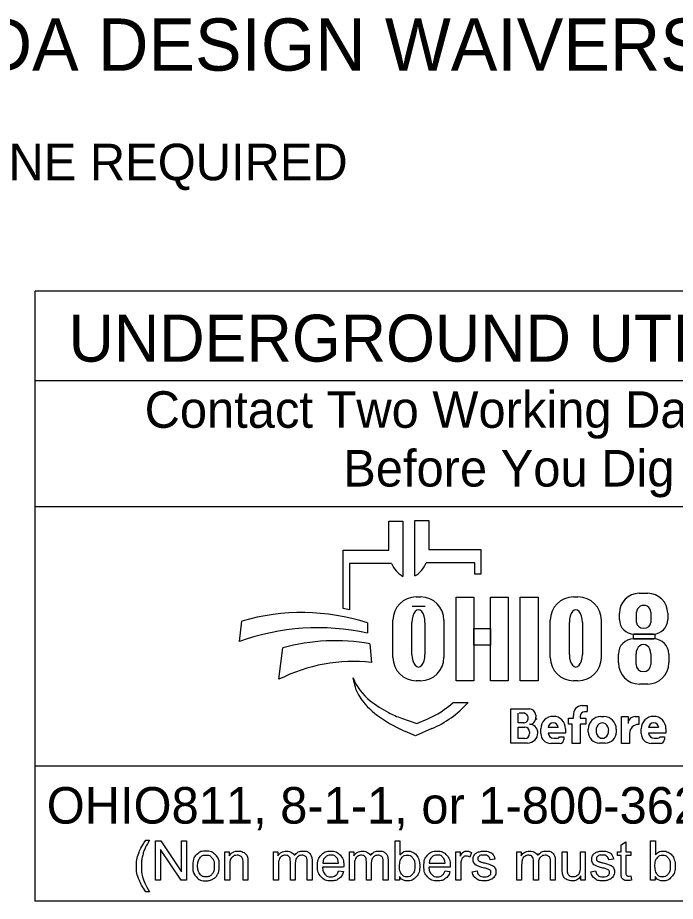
# Model space of a CAD drawing. Extents: x -1.8 to 75.7, y -2 to 25.
# Drawn here: x 44.011 to 46.531, y 3.755 to 7.141 of the extents above; entities that cross this region are included whole.
import ezdxf

# ---------------------------------------------------------------- set-up
doc = ezdxf.new("R2010")
doc.units = 0
doc.layers.add('SH_Data', color=7, linetype='Continuous')
doc.layers.add('SH_Text', color=7, linetype='Continuous')

msp = doc.modelspace()

# ---------------------------------------------------------------- linework, layer by layer
at = {"layer": 'SH_Data'}
for p, q in [((44.0777, 3.7549), (44.0777, 6.0924)), ((48.3277, 6.0924), (44.0777, 6.0924)), ((44.0777, 5.7508), (48.3277, 5.7508)), ((44.0777, 5.2674), (48.3277, 5.2674)), ((48.3277, 4.2727), (44.0777, 4.2727)), ((48.3277, 3.7549), (44.0777, 3.7549))]:
    msp.add_line(p, q, dxfattribs=at)
at = {"layer": 'SH_Text'}
for p, q in [((45.533, 5.0021), (45.533, 5.2142)), ((45.533, 5.2142), (45.5866, 5.2142)), ((45.5866, 5.2142), (45.5866, 5.1027)), ((45.4337, 5.1004), (45.4337, 5.2119)), ((45.4337, 5.2119), (45.4873, 5.2119)), ((45.4873, 5.2119), (45.4873, 4.9998)), ((45.2577, 4.8765), (45.2577, 5.1004)), ((45.2577, 5.1004), (45.4337, 5.1004)), ((45.5866, 5.1027), (45.7859, 5.1027)), ((45.7859, 5.1027), (45.7859, 5.0089)), ((45.283, 5.0489), (45.283, 4.8721)), ((45.4441, 5.0489), (45.283, 5.0489)), ((45.7626, 5.0513), (45.5762, 5.0513)), ((45.7626, 5.0089), (45.7626, 5.0513)), ((45.7859, 5.0089), (45.7626, 5.0089)), ((45.5387, 4.9212), (45.5552, 4.9212)), ((46.1417, 4.9212), (46.1583, 4.9212)), ((46.3933, 4.9352), (46.426, 4.9352)), ((45.572, 4.8842), (45.5222, 4.8842)), ((46.317, 4.8346), (46.317, 4.8589)), ((46.3831, 4.8232), (46.3831, 4.8625)), ((46.4373, 4.8625), (46.4373, 4.8232)), ((46.5023, 4.8589), (46.5023, 4.8346)), ((44.8604, 4.7502), (44.8698, 4.8283)), ((45.351, 4.8218), (45.351, 4.783)), ((45.4492, 4.6897), (45.4492, 4.8317)), ((45.5221, 4.7011), (45.5221, 4.8234)), ((45.5719, 4.8234), (45.5719, 4.7011)), ((45.6447, 4.8317), (45.6447, 4.6897)), ((46.0523, 4.6897), (46.0523, 4.8317)), ((46.1252, 4.7011), (46.1252, 4.8234)), ((46.175, 4.8234), (46.175, 4.7011)), ((46.2477, 4.8317), (46.2477, 4.6897)), ((46.4463, 4.7786), (46.373, 4.7786)), ((45.361, 4.7412), (45.3672, 4.6703)), ((46.3711, 4.7603), (46.4485, 4.7603)), ((45.0122, 4.6057), (45.0269, 4.7258)), ((46.3133, 4.6684), (46.3133, 4.7024)), ((46.3807, 4.6624), (46.3807, 4.7033)), ((46.4376, 4.7033), (46.4376, 4.6624)), ((46.5064, 4.7024), (46.5064, 4.6684)), ((45.2999, 4.5928), (45.2968, 4.6107)), ((45.5552, 4.6002), (45.5387, 4.6002)), ((46.1583, 4.6002), (46.1417, 4.6002)), ((46.4254, 4.5874), (46.3942, 4.5874)), ((45.6802, 4.5169), (45.7376, 4.5169)), ((46.1741, 4.5046), (46.1935, 4.5046)), ((46.1935, 4.5046), (46.1935, 4.4817)), ((45.9015, 4.3611), (45.9015, 4.4919)), ((45.9015, 4.4919), (45.9727, 4.4919)), ((45.9295, 4.4384), (45.9295, 4.4753)), ((45.9547, 4.4753), (45.9334, 4.4753)), ((46.1935, 4.4812), (46.1834, 4.4812)), ((45.4818, 4.4565), (45.5412, 4.436)), ((45.5412, 4.436), (45.5822, 4.4538)), ((45.9489, 4.4384), (45.9295, 4.4384)), ((45.9964, 4.4681), (45.9964, 4.4602)), ((46.1215, 4.4333), (46.1215, 4.4563)), ((46.1215, 4.4563), (46.1408, 4.4563)), ((46.1408, 4.4563), (46.1408, 4.4667)), ((46.1669, 4.4647), (46.1669, 4.4563)), ((46.1669, 4.4563), (46.1884, 4.4563)), ((46.1884, 4.4563), (46.1884, 4.4333)), ((46.2453, 4.4628), (46.2574, 4.4628)), ((46.3255, 4.3599), (46.3255, 4.4626)), ((46.3255, 4.4626), (46.3501, 4.4626)), ((46.3501, 4.4626), (46.3501, 4.4357)), ((46.3773, 4.4626), (46.3912, 4.4626)), ((46.3912, 4.4626), (46.3912, 4.433)), ((45.5352, 4.389), (45.4978, 4.4054)), ((45.5984, 4.4165), (45.5352, 4.389)), ((45.9295, 4.379), (45.9295, 4.4218)), ((45.9295, 4.4218), (45.955, 4.4218)), ((45.9731, 4.4037), (45.9731, 4.3973)), ((46.016, 4.3979), (46.016, 4.4163)), ((46.0826, 4.4203), (46.0441, 4.4203)), ((46.1106, 4.4163), (46.1106, 4.3987)), ((46.1364, 4.4333), (46.1215, 4.4333)), ((46.1364, 4.3599), (46.1364, 4.4333)), ((46.1884, 4.4333), (46.1669, 4.4333)), ((46.1669, 4.4333), (46.1669, 4.3599)), ((46.1975, 4.4042), (46.1975, 4.415)), ((46.3052, 4.415), (46.3052, 4.4042)), ((46.401, 4.3979), (46.401, 4.4163)), ((46.4675, 4.4203), (46.429, 4.4203)), ((46.4955, 4.4163), (46.4955, 4.3987)), ((45.9547, 4.379), (45.9295, 4.379)), ((46.0045, 4.4008), (46.0045, 4.4005)), ((46.1106, 4.3987), (46.0441, 4.3987)), ((46.0651, 4.3794), (46.0792, 4.3794)), ((46.0878, 4.385), (46.1046, 4.385)), ((46.1046, 4.385), (46.1046, 4.3752)), ((46.3561, 4.3981), (46.3561, 4.3599)), ((46.4955, 4.3987), (46.4291, 4.3987)), ((46.45, 4.3794), (46.4641, 4.3794)), ((46.4727, 4.385), (46.4895, 4.385)), ((46.4895, 4.385), (46.4895, 4.3752)), ((45.9651, 4.3611), (45.9015, 4.3611)), ((46.0894, 4.3599), (46.054, 4.3599)), ((46.1669, 4.3599), (46.1364, 4.3599)), ((46.2625, 4.3615), (46.2402, 4.3615)), ((46.3561, 4.3599), (46.3255, 4.3599)), ((46.4743, 4.3599), (46.4389, 4.3599))]:
    msp.add_line(p, q, dxfattribs=at)
for points in [[(45.6911, 4.9201), (45.7591, 4.9201), (45.7591, 4.6002), (45.6911, 4.6002)], [(45.8233, 4.9201), (45.8912, 4.9201), (45.8912, 4.6002), (45.8233, 4.6002)], [(45.9366, 4.9201), (46.0054, 4.9201), (46.0054, 4.6002), (45.9366, 4.6002)], [(45.7591, 4.8003), (45.8233, 4.8003), (45.8233, 4.7363), (45.7591, 4.7363)], [(46.3708, 4.7786), (46.4525, 4.7786), (46.4525, 4.7601), (46.3708, 4.7601)]]:
    msp.add_lwpolyline(points, close=True, dxfattribs=at)
for points in [[(44.5023, 3.9887), (44.5155, 3.9887)], [(44.539, 3.836), (44.539, 3.9862), (44.5594, 3.9862), (44.6384, 3.8682), (44.6384, 3.9862), (44.6574, 3.9862), (44.6574, 3.836), (44.637, 3.836), (44.558, 3.9539), (44.558, 3.836), (44.539, 3.836)], [(45.4745, 3.836), (45.4574, 3.836), (45.4574, 3.9862), (45.4759, 3.9862), (45.4759, 3.9326)], [(46.3234, 3.8679), (46.3234, 3.9305), (46.3098, 3.9305), (46.3098, 3.9448), (46.3234, 3.9448), (46.3234, 3.9718), (46.3419, 3.9828), (46.3419, 3.9448), (46.3603, 3.9448), (46.3603, 3.9305), (46.3419, 3.9305), (46.3419, 3.8668)], [(46.4536, 3.836), (46.4365, 3.836), (46.4365, 3.9862), (46.4549, 3.9862), (46.4549, 3.9326)], [(44.805, 3.836), (44.805, 3.9448), (44.8216, 3.9448), (44.8216, 3.9294)], [(44.9914, 3.836), (44.9914, 3.9448), (45.0079, 3.9448), (45.0079, 3.9295)], [(45.2828, 3.836), (45.2828, 3.9448), (45.2993, 3.9448), (45.2993, 3.9295)], [(45.6906, 3.836), (45.6906, 3.9448), (45.7072, 3.9448), (45.7072, 3.9283)], [(45.7496, 3.9414), (45.7432, 3.9243)], [(45.9238, 3.836), (45.9238, 3.9448), (45.9403, 3.9448), (45.9403, 3.9295)], [(46.0981, 3.8774), (46.0981, 3.9448), (46.1165, 3.9448), (46.1165, 3.8845)], [(46.1678, 3.8866), (46.1678, 3.9448), (46.1862, 3.9448), (46.1862, 3.836), (46.1697, 3.836)], [(44.8234, 3.8954), (44.8234, 3.836), (44.805, 3.836)], [(44.8934, 3.9029), (44.8934, 3.836), (44.8749, 3.836), (44.8749, 3.9021)], [(45.0745, 3.8992), (45.0745, 3.836), (45.0561, 3.836), (45.0561, 3.9067)], [(45.1389, 3.9107), (45.1389, 3.836), (45.1205, 3.836), (45.1205, 3.9045)], [(45.18, 3.9008), (45.2408, 3.9008)], [(45.3659, 3.8992), (45.3659, 3.836), (45.3474, 3.836), (45.3474, 3.9067)], [(45.4303, 3.9107), (45.4303, 3.836), (45.4119, 3.836), (45.4119, 3.9045)], [(45.588, 3.9008), (45.6488, 3.9008)], [(45.8396, 3.9167), (45.8215, 3.9143)], [(46.0069, 3.8992), (46.0069, 3.836), (45.9884, 3.836), (45.9884, 3.9067)], [(46.0713, 3.9107), (46.0713, 3.836), (46.0529, 3.836), (46.0529, 3.9045)], [(46.2941, 3.9167), (46.2761, 3.9143)], [(45.0098, 3.8924), (45.0098, 3.836), (44.9914, 3.836)], [(45.2602, 3.8857), (45.179, 3.8857)], [(45.2406, 3.8711), (45.2596, 3.8687)], [(45.3012, 3.8924), (45.3012, 3.836), (45.2828, 3.836)], [(45.6681, 3.8857), (45.587, 3.8857)], [(45.6486, 3.8711), (45.6676, 3.8687)], [(45.709, 3.893), (45.709, 3.836), (45.6906, 3.836)], [(45.7532, 3.8685), (45.7714, 3.8714)], [(45.9422, 3.8924), (45.9422, 3.836), (45.9238, 3.836)], [(46.2077, 3.8685), (46.2259, 3.8714)], [(45.4745, 3.8496), (45.4745, 3.836)], [(46.1697, 3.836), (46.1697, 3.8521)], [(46.3603, 3.8524), (46.3629, 3.8362)], [(46.4536, 3.8496), (46.4536, 3.836)], [(44.5155, 3.7918), (44.5023, 3.7918)]]:
    msp.add_lwpolyline(points, dxfattribs=at)
for centre, radius, start, end in [((45.5355, 5.0857), 0.0985, 201.9296, 240.7469), ((45.4849, 5.088), 0.0985, 299.2531, 338.0704), ((45.5387, 4.8317), 0.0895, 90, 180), ((45.5552, 4.8317), 0.0895, 0, 90), ((46.1417, 4.8317), 0.0895, 90, 180), ((46.1583, 4.8317), 0.0895, 0, 90), ((46.3933, 4.8589), 0.0763, 90, 180), ((46.426, 4.8589), 0.0763, 0, 90), ((45.1296, 4.0675), 0.8191, 79.2074, 81.0007), ((45.0999, 4.0422), 0.8191, 72.1402, 106.3144), ((46.373, 4.8346), 0.056, 180, 270), ((46.4463, 4.8346), 0.056, 270, 0), ((45.1629, 3.9111), 0.8919, 77.8238, 109.8274), ((45.2268, 4.0214), 0.7322, 79.44, 105.8467), ((46.3711, 4.7024), 0.0579, 90, 180), ((46.4485, 4.7024), 0.0579, 0, 90), ((45.2989, 4.0382), 0.6357, 83.8248, 116.8021), ((45.5387, 4.6897), 0.0895, 180, 270), ((45.5552, 4.6897), 0.0895, 270, 0), ((46.1417, 4.6897), 0.0895, 180, 270), ((46.1583, 4.6897), 0.0895, 270, 0), ((46.3942, 4.6684), 0.081, 180, 270), ((46.4254, 4.6684), 0.081, 270, 0), ((45.4842, 4.6828), 0.2008, 201.0457, 232.5314), ((45.4412, 4.6169), 0.1433, 189.6817, 216.0884), ((45.5749, 4.7143), 0.3088, 216.0884, 235.7167), ((45.6768, 4.934), 0.5173, 232.5314, 241.794), ((45.4388, 4.7843), 0.3602, 293.4582, 312.0712), ((45.4388, 4.7843), 0.401, 293.4582, 317.8286), ((46.1741, 4.4711), 0.0335, 90, 187.5187), ((45.5916, 4.7752), 0.3371, 241.794, 250.9821), ((45.9507, 4.4584), 0.0169, 357.8325, 90), ((45.9727, 4.4681), 0.0238, 0, 90), ((46.1834, 4.4647), 0.0165, 90, 180), ((45.7414, 4.9585), 0.6044, 235.7167, 246.2325), ((45.9489, 4.4571), 0.0187, 270, 2.0582), ((45.9723, 4.4574), 0.0243, 270, 6.6529), ((45.9828, 4.4559), 0.0175, 347.4023, 0), ((46.0633, 4.4163), 0.0473, 0, 180), ((46.0633, 4.4193), 0.0193, 2.9632, 177.0368), ((46.2453, 4.415), 0.0478, 90, 180), ((46.2574, 4.415), 0.0478, 0, 90), ((46.377, 4.4357), 0.0269, 89.2449, 180), ((46.4482, 4.4163), 0.0473, 0, 180), ((46.4483, 4.4193), 0.0193, 2.9632, 177.0368), ((45.955, 4.4037), 0.0181, 0, 90), ((45.9724, 4.401), 0.0321, 4.0748, 90), ((45.9715, 4.4008), 0.033, 0, 11.7502), ((46.2402, 4.4042), 0.0428, 180, 270), ((46.2625, 4.4042), 0.0428, 270, 0), ((46.391, 4.3981), 0.0349, 89.6033, 180), ((45.9547, 4.3973), 0.0184, 270, 0), ((45.9651, 4.4005), 0.0393, 270, 0), ((46.054, 4.3979), 0.038, 180, 270), ((46.0651, 4.4004), 0.021, 184.827, 270), ((46.0792, 4.3888), 0.00938, 270, 335.9979), ((46.0894, 4.3752), 0.0152, 270, 0), ((46.4389, 4.3979), 0.038, 180, 270), ((46.45, 4.4004), 0.021, 184.827, 270), ((46.4641, 4.3888), 0.00938, 270, 335.9979), ((46.4743, 4.3752), 0.0152, 270, 0)]:
    msp.add_arc(centre, radius, start, end, dxfattribs=at)
for centre, major_axis, ratio, start_param, end_param in [((46.4102, 4.8625), (0.0271, 0), 0.969373, 0, 3.141593), ((45.547, 4.8234), (0, 0.0484), 0.514403, 4.712389, 7.853982), ((46.1501, 4.8234), (0, 0.0484), 0.514403, 4.712389, 7.853982), ((46.4102, 4.8232), (0.0271, 0), 0.818453, 3.141593, 6.283185), ((46.4092, 4.7033), (0, 0.0358), 0.794529, 4.712389, 7.853982), ((45.547, 4.7011), (0, 0.0484), 0.514403, 1.570796, 4.712389), ((46.1501, 4.7011), (0, 0.0484), 0.514403, 1.570796, 4.712389), ((46.4092, 4.6624), (0.0284, 0), 0.959837, 3.141593, 6.283185), ((46.2518, 4.4096), (0, 0.029), 0.832186, 4.712389, 7.853982), ((46.2518, 4.4096), (0, 0.0302), 0.797287, 1.570796, 4.712389)]:
    msp.add_ellipse(centre, major_axis=major_axis, ratio=ratio, start_param=start_param, end_param=end_param, dxfattribs=at)
for points in [[(44.5023, 3.7918), (44.487, 3.8111), (44.4765, 3.8369), (44.4659, 3.8627), (44.4659, 3.8904), (44.4659, 3.9147), (44.4738, 3.9371), (44.483, 3.963), (44.5023, 3.9887)], [(44.5155, 3.9887), (44.5031, 3.9674), (44.4991, 3.9583), (44.4929, 3.9441), (44.4893, 3.9288), (44.4849, 3.9096), (44.4849, 3.8903), (44.4849, 3.841), (44.5155, 3.7918)], [(44.6815, 3.8904), (44.6815, 3.9206), (44.6983, 3.9352), (44.7123, 3.9472), (44.7325, 3.9472), (44.7549, 3.9472), (44.7691, 3.9326), (44.7834, 3.9179), (44.7834, 3.892), (44.7834, 3.871), (44.7771, 3.8589), (44.7708, 3.8469), (44.7588, 3.8403), (44.7467, 3.8336), (44.7325, 3.8336), (44.7097, 3.8336), (44.6956, 3.8482), (44.6815, 3.8629), (44.6815, 3.8904)], [(44.7005, 3.8904), (44.7005, 3.8695), (44.7096, 3.8591), (44.7187, 3.8487), (44.7325, 3.8487), (44.7462, 3.8487), (44.7553, 3.8592), (44.7644, 3.8696), (44.7644, 3.891), (44.7644, 3.9112), (44.7552, 3.9216), (44.7461, 3.932), (44.7325, 3.932), (44.7187, 3.932), (44.7096, 3.9217), (44.7005, 3.9113), (44.7005, 3.8904)], [(44.8216, 3.9294), (44.8336, 3.9472), (44.8562, 3.9472), (44.866, 3.9472), (44.8743, 3.9437), (44.8825, 3.9402), (44.8866, 3.9344), (44.8907, 3.9287), (44.8923, 3.9208), (44.8934, 3.9157), (44.8934, 3.9029)], [(44.8749, 3.9021), (44.8749, 3.9134), (44.8728, 3.919), (44.8706, 3.9246), (44.8651, 3.9279), (44.8597, 3.9312), (44.8523, 3.9312), (44.8405, 3.9312), (44.832, 3.9237), (44.8234, 3.9163), (44.8234, 3.8954)], [(45.0079, 3.9295), (45.013, 3.9375), (45.0215, 3.9424), (45.03, 3.9472), (45.0409, 3.9472), (45.053, 3.9472), (45.0607, 3.9422), (45.0685, 3.9372), (45.0716, 3.9282), (45.0846, 3.9472), (45.1053, 3.9472), (45.1215, 3.9472), (45.1302, 3.9383), (45.1389, 3.9293), (45.1389, 3.9107)], [(45.0561, 3.9067), (45.0561, 3.9189), (45.0516, 3.9251), (45.0471, 3.9312), (45.0368, 3.9312), (45.029, 3.9312), (45.0224, 3.9271), (45.0158, 3.923), (45.0128, 3.9151), (45.0098, 3.9073), (45.0098, 3.8924)], [(45.1205, 3.9045), (45.1205, 3.9156), (45.1187, 3.9204), (45.1169, 3.9253), (45.1122, 3.9283), (45.1075, 3.9312), (45.1011, 3.9312), (45.0897, 3.9312), (45.0821, 3.9236), (45.0745, 3.916), (45.0745, 3.8992)], [(45.2596, 3.8687), (45.2551, 3.852), (45.243, 3.8428), (45.2308, 3.8336), (45.2118, 3.8336), (45.188, 3.8336), (45.174, 3.8483), (45.16, 3.863), (45.16, 3.8895), (45.16, 3.9169), (45.1741, 3.9321), (45.1883, 3.9472), (45.2108, 3.9472), (45.2326, 3.9472), (45.2464, 3.9324), (45.2603, 3.9175), (45.2603, 3.8906), (45.2603, 3.889), (45.2602, 3.8857)], [(45.2408, 3.9008), (45.2396, 3.9146), (45.2338, 3.9214), (45.225, 3.9321), (45.211, 3.9321), (45.1983, 3.9321), (45.1896, 3.9236), (45.181, 3.9151), (45.18, 3.9008)], [(45.2993, 3.9295), (45.3044, 3.9375), (45.3129, 3.9424), (45.3214, 3.9472), (45.3323, 3.9472), (45.3444, 3.9472), (45.3521, 3.9422), (45.3598, 3.9372), (45.363, 3.9282), (45.3759, 3.9472), (45.3967, 3.9472), (45.4129, 3.9472), (45.4216, 3.9383), (45.4303, 3.9293), (45.4303, 3.9107)], [(45.3474, 3.9067), (45.3474, 3.9189), (45.3429, 3.9251), (45.3384, 3.9312), (45.3282, 3.9312), (45.3204, 3.9312), (45.3138, 3.9271), (45.3072, 3.923), (45.3042, 3.9151), (45.3012, 3.9073), (45.3012, 3.8924)], [(45.4119, 3.9045), (45.4119, 3.9156), (45.4101, 3.9204), (45.4083, 3.9253), (45.4036, 3.9283), (45.3989, 3.9312), (45.3925, 3.9312), (45.381, 3.9312), (45.3735, 3.9236), (45.3659, 3.916), (45.3659, 3.8992)], [(45.4743, 3.8912), (45.4743, 3.8717), (45.4796, 3.863), (45.4883, 3.8487), (45.5031, 3.8487), (45.5152, 3.8487), (45.524, 3.8592), (45.5327, 3.8697), (45.5327, 3.8905), (45.5327, 3.9118), (45.5243, 3.922), (45.5159, 3.9321), (45.5039, 3.9321), (45.4919, 3.9321), (45.4831, 3.9216), (45.4743, 3.9111), (45.4743, 3.8912)], [(45.4759, 3.9326), (45.4875, 3.9472), (45.5057, 3.9472), (45.5157, 3.9472), (45.5247, 3.9432), (45.5336, 3.9392), (45.5394, 3.9318), (45.5452, 3.9245), (45.5485, 3.9142), (45.5517, 3.9038), (45.5517, 3.8921), (45.5517, 3.8641), (45.5379, 3.8489), (45.5241, 3.8336), (45.5047, 3.8336), (45.4855, 3.8336), (45.4745, 3.8496)], [(45.6676, 3.8687), (45.6631, 3.852), (45.6509, 3.8428), (45.6388, 3.8336), (45.6198, 3.8336), (45.596, 3.8336), (45.582, 3.8483), (45.568, 3.863), (45.568, 3.8895), (45.568, 3.9169), (45.5821, 3.9321), (45.5963, 3.9472), (45.6188, 3.9472), (45.6406, 3.9472), (45.6544, 3.9324), (45.6682, 3.9175), (45.6682, 3.8906), (45.6682, 3.889), (45.6681, 3.8857)], [(45.6488, 3.9008), (45.6476, 3.9146), (45.6418, 3.9214), (45.633, 3.9321), (45.619, 3.9321), (45.6063, 3.9321), (45.5976, 3.9236), (45.5889, 3.9151), (45.588, 3.9008)], [(45.7072, 3.9283), (45.7135, 3.9399), (45.7189, 3.9436), (45.7242, 3.9472), (45.7307, 3.9472), (45.74, 3.9472), (45.7496, 3.9414)], [(45.7432, 3.9243), (45.7364, 3.9282), (45.7297, 3.9282), (45.7237, 3.9282), (45.7189, 3.9246), (45.7141, 3.921), (45.7121, 3.9145), (45.709, 3.9047), (45.709, 3.893)], [(45.8215, 3.9143), (45.8203, 3.9227), (45.8144, 3.9274), (45.8085, 3.9321), (45.7977, 3.9321), (45.785, 3.9321), (45.7795, 3.9279), (45.7741, 3.9237), (45.7741, 3.9181), (45.7741, 3.9145), (45.7764, 3.9116), (45.7786, 3.9086), (45.7834, 3.9067), (45.7862, 3.9057), (45.7997, 3.902), (45.8193, 3.8968), (45.8271, 3.8934), (45.8349, 3.8901), (45.8393, 3.8838), (45.8437, 3.8774), (45.8437, 3.868), (45.8437, 3.8588), (45.8383, 3.8506), (45.8329, 3.8425), (45.8228, 3.8381), (45.8126, 3.8336), (45.7998, 3.8336), (45.7785, 3.8336), (45.7674, 3.8424), (45.7562, 3.8512), (45.7532, 3.8685)], [(45.7714, 3.8714), (45.7729, 3.8604), (45.7799, 3.8546), (45.787, 3.8487), (45.7996, 3.8487), (45.8124, 3.8487), (45.8185, 3.8539), (45.8247, 3.8591), (45.8247, 3.866), (45.8247, 3.8723), (45.8192, 3.8759), (45.8154, 3.8784), (45.8004, 3.8822), (45.7801, 3.8873), (45.7722, 3.891), (45.7644, 3.8947), (45.7603, 3.9013), (45.7563, 3.9079), (45.7563, 3.9159), (45.7563, 3.9232), (45.7596, 3.9294), (45.7629, 3.9356), (45.7687, 3.9397), (45.773, 3.9428), (45.7804, 3.945), (45.7879, 3.9472), (45.7964, 3.9472), (45.8092, 3.9472), (45.8189, 3.9436), (45.8286, 3.9399), (45.8332, 3.9336), (45.8378, 3.9272), (45.8396, 3.9167)], [(45.9403, 3.9295), (45.9454, 3.9375), (45.9539, 3.9424), (45.9624, 3.9472), (45.9733, 3.9472), (45.9854, 3.9472), (45.9931, 3.9422), (46.0008, 3.9372), (46.004, 3.9282), (46.0169, 3.9472), (46.0377, 3.9472), (46.0539, 3.9472), (46.0626, 3.9383), (46.0713, 3.9293), (46.0713, 3.9107)], [(45.9884, 3.9067), (45.9884, 3.9189), (45.9839, 3.9251), (45.9794, 3.9312), (45.9692, 3.9312), (45.9614, 3.9312), (45.9548, 3.9271), (45.9482, 3.923), (45.9452, 3.9151), (45.9422, 3.9073), (45.9422, 3.8924)], [(46.0529, 3.9045), (46.0529, 3.9156), (46.0511, 3.9204), (46.0493, 3.9253), (46.0446, 3.9283), (46.0399, 3.9312), (46.0335, 3.9312), (46.022, 3.9312), (46.0145, 3.9236), (46.0069, 3.916), (46.0069, 3.8992)], [(46.2761, 3.9143), (46.2748, 3.9227), (46.2689, 3.9274), (46.263, 3.9321), (46.2523, 3.9321), (46.2396, 3.9321), (46.2341, 3.9279), (46.2287, 3.9237), (46.2287, 3.9181), (46.2287, 3.9145), (46.2309, 3.9116), (46.2332, 3.9086), (46.238, 3.9067), (46.2408, 3.9057), (46.2543, 3.902), (46.2739, 3.8968), (46.2817, 3.8934), (46.2894, 3.8901), (46.2938, 3.8838), (46.2983, 3.8774), (46.2983, 3.868), (46.2983, 3.8588), (46.2929, 3.8506), (46.2875, 3.8425), (46.2773, 3.8381), (46.2672, 3.8336), (46.2543, 3.8336), (46.2331, 3.8336), (46.222, 3.8424), (46.2108, 3.8512), (46.2077, 3.8685)], [(46.2259, 3.8714), (46.2275, 3.8604), (46.2345, 3.8546), (46.2416, 3.8487), (46.2542, 3.8487), (46.2669, 3.8487), (46.2731, 3.8539), (46.2793, 3.8591), (46.2793, 3.866), (46.2793, 3.8723), (46.2738, 3.8759), (46.27, 3.8784), (46.2549, 3.8822), (46.2346, 3.8873), (46.2268, 3.891), (46.2189, 3.8947), (46.2149, 3.9013), (46.2108, 3.9079), (46.2108, 3.9159), (46.2108, 3.9232), (46.2142, 3.9294), (46.2175, 3.9356), (46.2232, 3.9397), (46.2276, 3.9428), (46.235, 3.945), (46.2424, 3.9472), (46.2509, 3.9472), (46.2638, 3.9472), (46.2735, 3.9436), (46.2832, 3.9399), (46.2878, 3.9336), (46.2924, 3.9272), (46.2941, 3.9167)], [(46.4533, 3.8912), (46.4533, 3.8717), (46.4586, 3.863), (46.4673, 3.8487), (46.4822, 3.8487), (46.4942, 3.8487), (46.503, 3.8592), (46.5118, 3.8697), (46.5118, 3.8905), (46.5118, 3.9118), (46.5034, 3.922), (46.4949, 3.9321), (46.483, 3.9321), (46.4709, 3.9321), (46.4621, 3.9216), (46.4533, 3.9111), (46.4533, 3.8912)], [(46.4549, 3.9326), (46.4666, 3.9472), (46.4847, 3.9472), (46.4948, 3.9472), (46.5037, 3.9432), (46.5127, 3.9392), (46.5185, 3.9318), (46.5243, 3.9245), (46.5275, 3.9142), (46.5308, 3.9038), (46.5308, 3.8921), (46.5308, 3.8641), (46.517, 3.8489), (46.5031, 3.8336), (46.4838, 3.8336), (46.4645, 3.8336), (46.4536, 3.8496)], [(45.179, 3.8857), (45.18, 3.8678), (45.1891, 3.8582), (45.1983, 3.8487), (45.2119, 3.8487), (45.222, 3.8487), (45.2292, 3.8541), (45.2364, 3.8594), (45.2406, 3.8711)], [(45.587, 3.8857), (45.588, 3.8678), (45.5971, 3.8582), (45.6063, 3.8487), (45.6199, 3.8487), (45.63, 3.8487), (45.6372, 3.8541), (45.6444, 3.8594), (45.6486, 3.8711)], [(46.1697, 3.8521), (46.1571, 3.8336), (46.1353, 3.8336), (46.1256, 3.8336), (46.1173, 3.8373), (46.1089, 3.841), (46.1049, 3.8466), (46.1009, 3.8521), (46.0992, 3.8602), (46.0981, 3.8657), (46.0981, 3.8774)], [(46.1165, 3.8845), (46.1165, 3.8701), (46.1177, 3.8651), (46.1194, 3.8578), (46.125, 3.8537), (46.1306, 3.8495), (46.1389, 3.8495), (46.1472, 3.8495), (46.1545, 3.8538), (46.1618, 3.858), (46.1648, 3.8653), (46.1678, 3.8727), (46.1678, 3.8866)], [(46.3629, 3.8362), (46.3551, 3.8345), (46.349, 3.8345), (46.339, 3.8345), (46.3335, 3.8377), (46.3279, 3.8409), (46.3257, 3.8461), (46.3234, 3.8512), (46.3234, 3.8679)], [(46.3419, 3.8668), (46.3419, 3.8589), (46.3428, 3.8566), (46.3438, 3.8544), (46.346, 3.853), (46.3482, 3.8517), (46.3522, 3.8517), (46.3553, 3.8517), (46.3603, 3.8524)]]:
    msp.add_open_spline(points, degree=3, dxfattribs=at)

# ---------------------------------------------------------------- texts
for s, height, p in [('ADA DESIGN WAIVERS', 0.2, (43.6946, 6.9377)), ('NONE REQUIRED', 0.14, (43.6946, 6.5177)), ('UNDERGROUND UTILITIES', 0.18, (44.2058, 5.8227)), ('Contact Two Working Days', 0.14, (44.4973, 5.5692)), ('Before You Dig', 0.14, (45.2585, 5.3442)), ('OHIO811, 8-1-1, or 1-800-362-2764', 0.14, (44.1221, 4.0527))]:
    msp.add_text(s, height=height, dxfattribs=at).set_placement(p)

doc.saveas('drawing.dxf')
